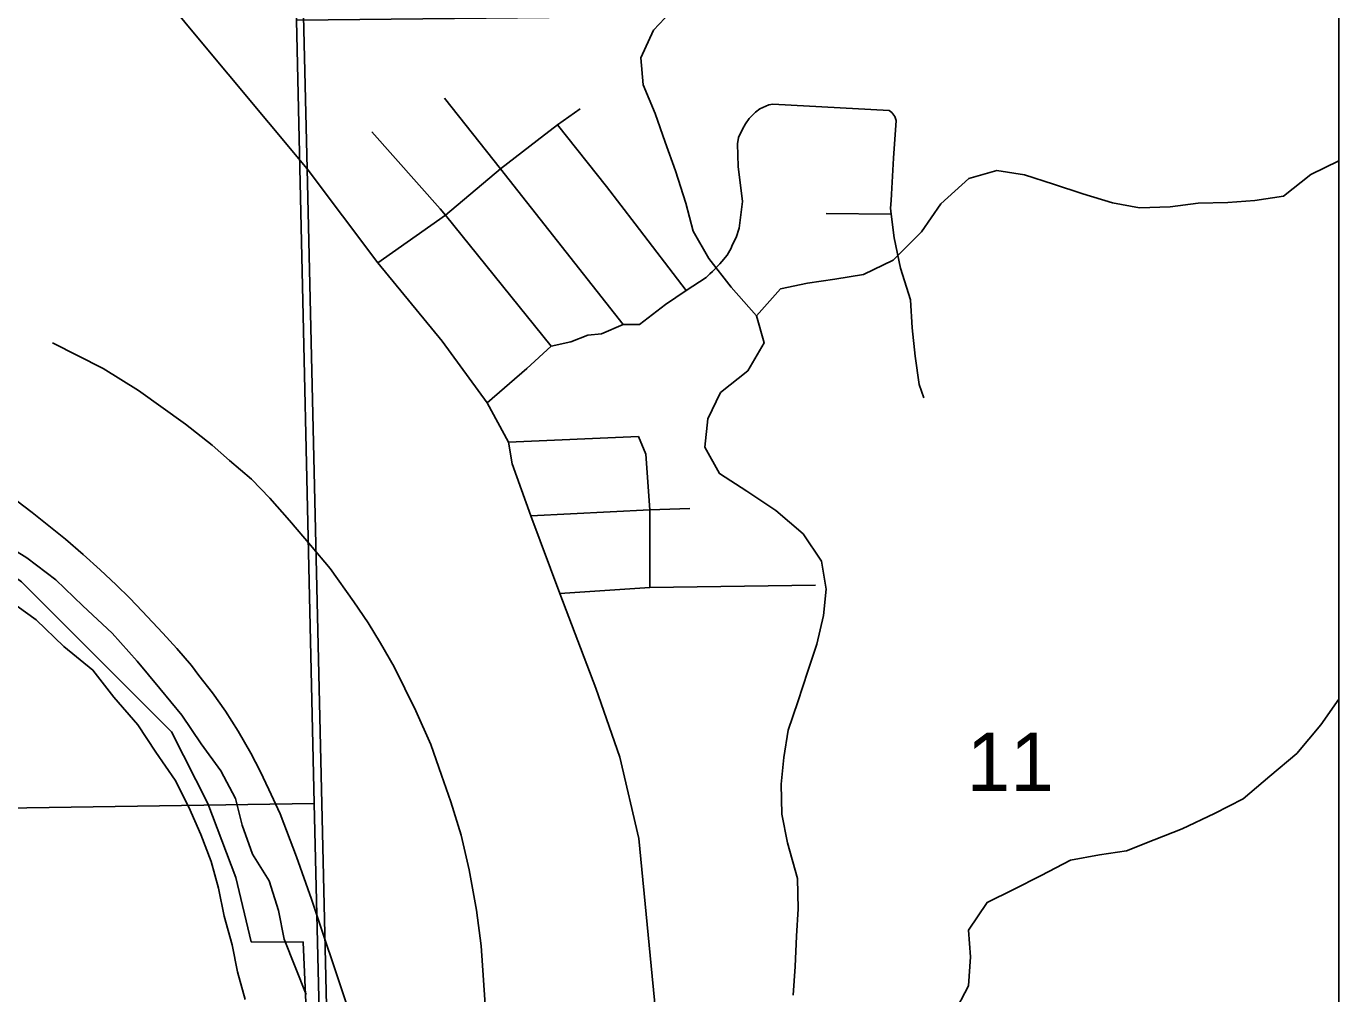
# Model space of a CAD drawing. Extents: x -37878.7 to -37844.7, y -19791.4 to -19769.4.
# Drawn here: x -37870.09 to -37869.15, y -19776.447 to -19775.754 of the extents above; entities that cross this region are included whole.
import ezdxf

# ---------------------------------------------------------------- set-up
doc = ezdxf.new("R2010")
doc.units = 0
for name, color, linetype in [('GM_X_City_Street', 7, 'Continuous'), ('GM_X_Corporation', 7, 'Continuous'), ('GM_X_Major_River', 7, 'Continuous'), ('GM_X_Minor_River', 7, 'Continuous'), ('GM_X_Rail_Line', 7, 'Continuous'), ('GM_X_Section', 7, 'Continuous'), ('GM_X_Section_Text', 7, 'Continuous'), ('GM_X_Township', 7, 'Continuous'), ('GM_X_US_Route', 7, 'Continuous'), ('SH_Data', 7, 'Continuous')]:
    doc.layers.add(name, color=color, linetype=linetype)

msp = doc.modelspace()

# ---------------------------------------------------------------- linework, layer by layer
at = {"layer": 'GM_X_City_Street'}
for points in [[(-37869.66271, -19775.96796), (-37869.75057, -19775.85654), (-37869.79065, -19775.80592)], [(-37869.59215, -19775.92285), (-37869.58828, -19775.91818), (-37869.58537, -19775.91331), (-37869.58476, -19775.91108), (-37869.58192, -19775.90562), (-37869.57969, -19775.89893), (-37869.57717, -19775.87985), (-37869.58049, -19775.85484), (-37869.58092, -19775.83851), (-37869.58005, -19775.83407), (-37869.57722, -19775.82799), (-37869.57524, -19775.82428), (-37869.57256, -19775.82031), (-37869.5681, -19775.81586), (-37869.56492, -19775.81335), (-37869.55839, -19775.8106), (-37869.55552, -19775.81006), (-37869.47237, -19775.81462), (-37869.47034, -19775.81612), (-37869.46832, -19775.81895), (-37869.46726, -19775.8217), (-37869.46919, -19775.84875), (-37869.47069, -19775.8746), (-37869.47095, -19775.87906)], [(-37869.72433, -19775.83618), (-37869.70981, -19775.82491), (-37869.69344, -19775.81345)], [(-37869.79387, -19775.88513), (-37869.84267, -19775.82983)], [(-37869.65418, -19775.89593), (-37869.67466, -19775.86919), (-37869.70981, -19775.82491)], [(-37869.83841, -19775.92369), (-37869.78994, -19775.88958), (-37869.75057, -19775.85654), (-37869.72433, -19775.83618)], [(-37869.71437, -19775.98342), (-37869.78994, -19775.88958), (-37869.79387, -19775.88513)], [(-37869.47095, -19775.87906), (-37869.47126, -19775.88455), (-37869.47076, -19775.8889), (-37869.4688, -19775.90578), (-37869.46405, -19775.9277), (-37869.457, -19775.95032), (-37869.45571, -19775.97044), (-37869.45365, -19775.99054), (-37869.45084, -19776.011), (-37869.44755, -19776.02041)], [(-37869.61761, -19775.94369), (-37869.65418, -19775.89593)], [(-37869.47076, -19775.8889), (-37869.51742, -19775.88848)], [(-37869.76012, -19776.02409), (-37869.7316, -19775.99959), (-37869.71437, -19775.98342), (-37869.70031, -19775.98026), (-37869.68802, -19775.97569), (-37869.67817, -19775.97464), (-37869.66271, -19775.96796), (-37869.65111, -19775.96796), (-37869.63245, -19775.95361), (-37869.61761, -19775.94369), (-37869.6034, -19775.93419), (-37869.60074, -19775.93174), (-37869.59874, -19775.9299), (-37869.59347, -19775.92444), (-37869.59215, -19775.92285)], [(-37869.74495, -19776.05231), (-37869.65181, -19776.0481)], [(-37869.64372, -19776.15636), (-37869.64372, -19776.10082), (-37869.64654, -19776.06075), (-37869.65181, -19776.0481)], [(-37869.72878, -19776.10504), (-37869.64372, -19776.10082), (-37869.61491, -19776.09977)], [(-37869.70805, -19776.16057), (-37869.64372, -19776.15636), (-37869.52493, -19776.1546)]]:
    msp.add_lwpolyline(points, dxfattribs=at)
at = {"layer": 'GM_X_Corporation'}
msp.add_lwpolyline([(-37871.03403, -19775.9918), (-37870.99201, -19775.97355), (-37870.94517, -19775.95099), (-37870.84307, -19775.92314), (-37870.77311, -19775.89957), (-37870.66134, -19775.87906), (-37870.60841, -19775.87192), (-37870.57174, -19775.88158), (-37870.49365, -19775.92282), (-37870.43119, -19775.96145), (-37870.34642, -19775.99718), (-37870.23698, -19776.04785), (-37870.09353, -19776.15235), (-37869.98605, -19776.25974), (-37869.96006, -19776.31113), (-37869.9401, -19776.36422), (-37869.92905, -19776.41032), (-37869.89186, -19776.41045), (-37869.85918, -19777.14892), (-37869.85397, -19777.32346), (-37869.91698, -19777.32303), (-37870.36299, -19777.3253), (-37870.36151, -19777.3854)], dxfattribs=at)
at = {"layer": 'GM_X_Major_River'}
for points in [[(-37870.10964, -19776.12293), (-37870.08965, -19776.13518), (-37870.06893, -19776.15085), (-37870.04974, -19776.16955), (-37870.02866, -19776.18901), (-37870.01061, -19776.20923), (-37869.99445, -19776.22867), (-37869.97867, -19776.24773)], [(-37870.10271, -19776.1655), (-37870.08311, -19776.17965), (-37870.06317, -19776.19873), (-37870.04245, -19776.21553), (-37870.02743, -19776.23498), (-37870.01014, -19776.2548), (-37869.99739, -19776.27423)], [(-37869.97867, -19776.24773), (-37869.96479, -19776.26831), (-37869.9509, -19776.28774), (-37869.94043, -19776.30754), (-37869.93563, -19776.32655), (-37869.92818, -19776.34747), (-37869.91619, -19776.36652), (-37869.90951, -19776.38782), (-37869.90547, -19776.40835), (-37869.88982, -19776.44792)], [(-37869.99739, -19776.27423), (-37869.9835, -19776.29443), (-37869.97378, -19776.31384), (-37869.9652, -19776.33325), (-37869.95775, -19776.35266), (-37869.95256, -19776.37167), (-37869.94853, -19776.39182), (-37869.9426, -19776.41235), (-37869.93893, -19776.43174), (-37869.93338, -19776.45152)]]:
    msp.add_lwpolyline(points, dxfattribs=at)
at = {"layer": 'GM_X_Minor_River'}
for points in [[(-37869.54113, -19776.44837), (-37869.53949, -19776.42787), (-37869.5386, -19776.40623), (-37869.53734, -19776.38648), (-37869.53796, -19776.36483), (-37869.54499, -19776.33935), (-37869.54903, -19776.31882), (-37869.54965, -19776.29717), (-37869.54764, -19776.27819), (-37869.54449, -19776.25846), (-37869.53755, -19776.23836), (-37869.53059, -19776.21636), (-37869.52404, -19776.19702), (-37869.51937, -19776.17653), (-37869.51736, -19776.15755), (-37869.52064, -19776.13741), (-37869.53377, -19776.11798), (-37869.55335, -19776.10118), (-37869.57409, -19776.08742), (-37869.5937, -19776.07479), (-37869.60418, -19776.05576), (-37869.60216, -19776.03564), (-37869.59296, -19776.01669), (-37869.57355, -19776.00121), (-37869.56169, -19775.98113), (-37869.56725, -19775.96174), (-37869.5853, -19775.94115), (-37869.60145, -19775.92057), (-37869.61269, -19775.90115), (-37869.61786, -19775.881), (-37869.62529, -19775.8578), (-37869.63273, -19775.83726), (-37869.6398, -19775.81672), (-37869.64838, -19775.79617), (-37869.65015, -19775.7768), (-37869.64095, -19775.75709), (-37869.62075, -19775.73554)], [(-37869.56725, -19775.96174), (-37869.55009, -19775.94245), (-37869.53076, -19775.93836), (-37869.51106, -19775.93541), (-37869.49059, -19775.93209), (-37869.46932, -19775.92193), (-37869.44913, -19775.90151), (-37869.43538, -19775.88145), (-37869.4152, -19775.86331), (-37869.3951, -19775.8577), (-37869.37543, -19775.86083), (-37869.35465, -19775.86738), (-37869.33349, -19775.87431), (-37869.31233, -19775.88086), (-37869.29304, -19775.88436), (-37869.27108, -19775.8837), (-37869.251, -19775.88113), (-37869.22979, -19775.88047), (-37869.21048, -19775.87903), (-37869.19001, -19775.87609), (-37869.17023, -19775.86061), (-37869.15036, -19775.85076)], [(-37869.42613, -19776.46218), (-37869.4154, -19776.44172), (-37869.41413, -19776.42084), (-37869.41553, -19776.40184), (-37869.40215, -19776.38215), (-37869.38316, -19776.37274), (-37869.36341, -19776.36258), (-37869.34252, -19776.35166), (-37869.32167, -19776.34795), (-37869.30235, -19776.345), (-37869.28261, -19776.33711), (-37869.26249, -19776.32922), (-37869.23933, -19776.31831), (-37869.21882, -19776.30777), (-37869.19979, -19776.29152), (-37869.18038, -19776.27528), (-37869.16321, -19776.25485), (-37869.15036, -19776.23625)]]:
    msp.add_lwpolyline(points, dxfattribs=at)
at = {"layer": 'GM_X_Rail_Line'}
for points in [[(-37869.76001, -19776.47638), (-37869.76439, -19776.41313), (-37869.76767, -19776.38752), (-37869.77292, -19776.35863), (-37869.77883, -19776.33368), (-37869.78605, -19776.30983), (-37869.79284, -19776.29079), (-37869.8005, -19776.2689), (-37869.81122, -19776.24461), (-37869.8191, -19776.22863), (-37869.82676, -19776.21331), (-37869.83639, -19776.19624), (-37869.84536, -19776.18158), (-37869.85565, -19776.1667), (-37869.8725, -19776.14284), (-37869.88651, -19776.12599), (-37869.90161, -19776.10848), (-37869.91583, -19776.09229), (-37869.92896, -19776.07872), (-37869.94472, -19776.06537), (-37869.95698, -19776.05443), (-37869.97602, -19776.03933), (-37870.00972, -19776.01525), (-37870.03511, -19775.9995), (-37870.07144, -19775.98111)], [(-37870.09677, -19776.09437), (-37870.086, -19776.1026), (-37870.07397, -19776.11231), (-37870.06214, -19776.12182), (-37870.04937, -19776.1328), (-37870.03722, -19776.14367), (-37870.02572, -19776.15455), (-37870.016, -19776.16405), (-37870.00703, -19776.17323), (-37869.99235, -19776.18907), (-37869.98222, -19776.20005), (-37869.97177, -19776.2123), (-37869.96649, -19776.21948), (-37869.95678, -19776.23172), (-37869.94738, -19776.24502), (-37869.93841, -19776.25928), (-37869.92933, -19776.27501), (-37869.92267, -19776.28799), (-37869.91655, -19776.30098), (-37869.90842, -19776.31861), (-37869.8966, -19776.34933), (-37869.88583, -19776.37974), (-37869.8606, -19776.45544)]]:
    msp.add_lwpolyline(points, dxfattribs=at)
at = {"layer": 'GM_X_Section'}
msp.add_lwpolyline([(-37869.91003, -19775.19003), (-37869.89663, -19775.75004), (-37869.88389, -19776.31106), (-37871.00738, -19776.32795), (-37871.03236, -19775.21238)], close=True, dxfattribs=at)
for points in [[(-37869.15036, -19776.78842), (-37869.87222, -19776.79874), (-37869.88389, -19776.31106), (-37869.89663, -19775.75004), (-37869.15036, -19775.742)], [(-37870.98026, -19777.3854), (-37871.00738, -19776.32795), (-37869.88389, -19776.31106), (-37869.87222, -19776.79874), (-37869.85861, -19777.3854)]]:
    msp.add_lwpolyline(points, dxfattribs=at)
at = {"layer": 'GM_X_Township'}
for points in [[(-37869.85249, -19777.3854), (-37869.85352, -19777.34229), (-37869.85397, -19777.32346), (-37869.85918, -19777.14892), (-37869.88906, -19775.85642), (-37869.89931, -19775.42763), (-37869.90245, -19775.29641), (-37869.90694, -19775.1088), (-37869.90874, -19775.03358), (-37869.90889, -19775.02744), (-37869.91269, -19774.86837)], [(-37869.91269, -19774.86837), (-37869.90889, -19775.02744), (-37869.90874, -19775.03358), (-37869.90694, -19775.1088), (-37869.90245, -19775.29641), (-37869.89931, -19775.42763), (-37869.88906, -19775.85642), (-37869.85918, -19777.14892), (-37869.85397, -19777.32346), (-37869.85352, -19777.34229), (-37869.85249, -19777.3854)]]:
    msp.add_lwpolyline(points, dxfattribs=at)
at = {"layer": 'GM_X_US_Route'}
msp.add_lwpolyline([(-37870.03845, -19775.67615), (-37869.97335, -19775.75551), (-37869.88906, -19775.85642), (-37869.83841, -19775.92369), (-37869.79226, -19775.98001), (-37869.76012, -19776.02409), (-37869.74495, -19776.05231), (-37869.74214, -19776.06778), (-37869.72878, -19776.10504), (-37869.70805, -19776.16057), (-37869.68242, -19776.22845), (-37869.66509, -19776.27787), (-37869.65162, -19776.33628), (-37869.63814, -19776.47428), (-37869.63312, -19776.54129), (-37869.62913, -19776.5618), (-37869.62344, -19776.58175), (-37869.59836, -19776.63189), (-37869.59164, -19776.64438)], dxfattribs=at)
at = {"layer": 'SH_Data'}
msp.add_line((-37869.15036, -19770.3854), (-37869.15036, -19777.3854), dxfattribs=at)

# ---------------------------------------------------------------- texts
at = {"layer": 'GM_X_Section_Text'}
msp.add_text('11', height=0.041856, rotation=0.00001, dxfattribs=at).set_placement((-37869.41669, -19776.30212))

doc.saveas('drawing.dxf')
